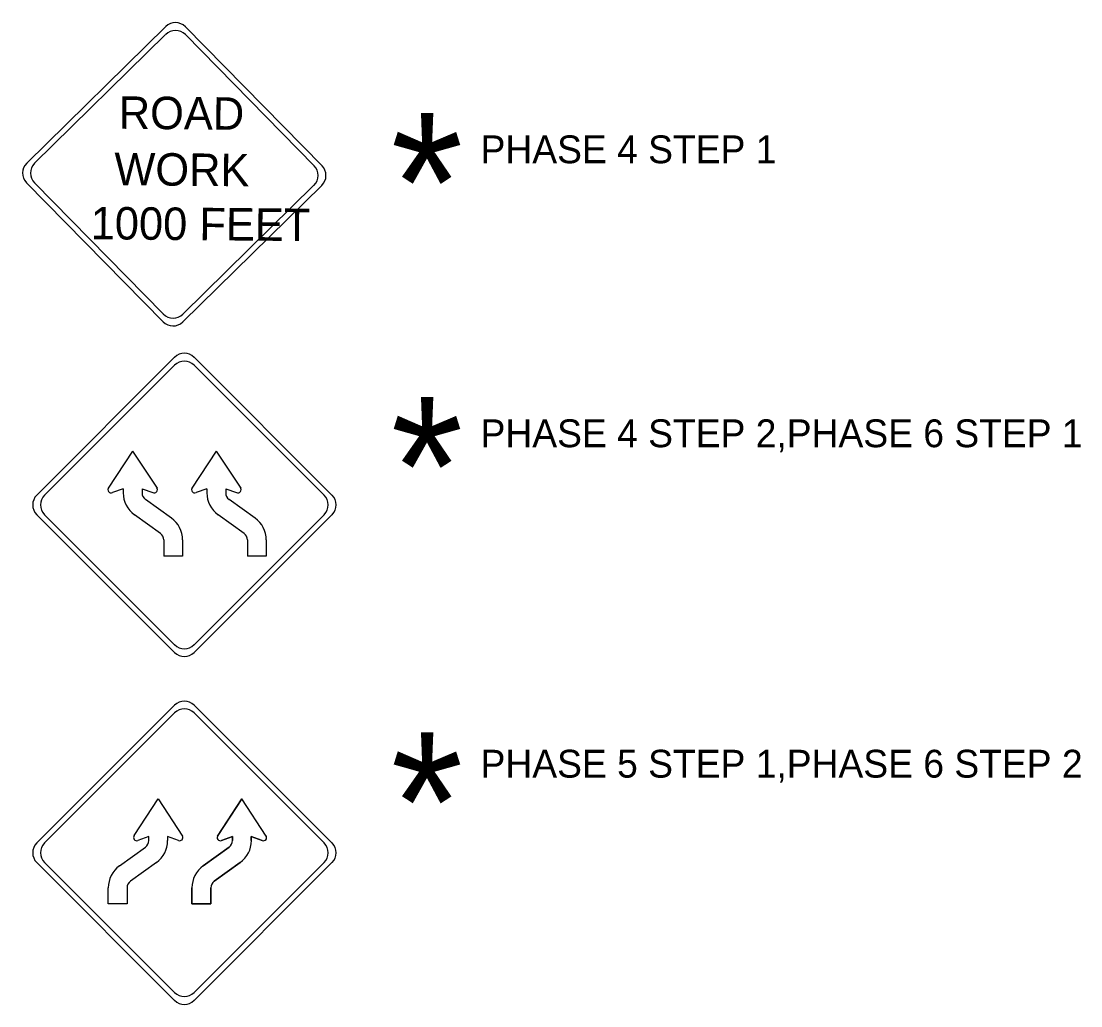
# Model space of a CAD drawing. Extents: x 2155255 to 2162649, y 140388 to 141878.
# Drawn here: x 2158429.7 to 2158658, y 141666 to 141878.2 of the extents above; entities that cross this region are included whole.
import ezdxf

# ---------------------------------------------------------------- set-up
doc = ezdxf.new("R2010")
doc.units = 0
for name, color, linetype in [('Default', 7, 'Continuous'), ('PR_Traffic_Control_Devices_Temp', 7, 'Continuous'), ('PR_Traffic_Control_Devices_Temp_Ph4', 7, 'Continuous')]:
    doc.layers.add(name, color=color, linetype=linetype)

# ---------------------------------------------------------------- blocks, each defined once
blk = doc.blocks.new('W1-4B(L)')
at = {"layer": 'Default'}
for p, q in [((0.0188, 0.2492), (0.2251, 0.4555)), ((0.4608, 0.2492), (0.2545, 0.4555)), ((0.0306, 0.2492), (0.2251, 0.4437)), ((0.449, 0.2492), (0.2545, 0.4437)), ((0.1624, 0.315), (0.1259, 0.2595)), ((0.1624, 0.315), (0.1259, 0.2595)), ((0.1624, 0.315), (0.1259, 0.2595)), ((0.1624, 0.315), (0.1989, 0.2595)), ((0.1624, 0.315), (0.1989, 0.2595)), ((0.1624, 0.315), (0.1989, 0.2595)), ((0.2876, 0.315), (0.2512, 0.2595)), ((0.2876, 0.315), (0.3241, 0.2595)), ((0.1483, 0.2586), (0.1321, 0.2529)), ((0.1483, 0.2586), (0.1321, 0.2529)), ((0.1483, 0.2586), (0.1321, 0.2529)), ((0.1483, 0.2586), (0.1483, 0.2526)), ((0.1483, 0.2586), (0.1483, 0.2526)), ((0.1483, 0.2586), (0.1483, 0.2526)), ((0.1765, 0.2586), (0.1765, 0.2526)), ((0.1765, 0.2586), (0.1927, 0.2529)), ((0.1765, 0.2586), (0.1765, 0.2526)), ((0.1765, 0.2586), (0.1927, 0.2529)), ((0.1765, 0.2586), (0.1765, 0.2526)), ((0.1765, 0.2586), (0.1927, 0.2529)), ((0.2735, 0.2586), (0.2573, 0.2529)), ((0.2735, 0.2586), (0.2735, 0.2526)), ((0.3017, 0.2586), (0.3017, 0.2526)), ((0.3017, 0.2586), (0.318, 0.2529)), ((0.2204, 0.2148), (0.1815, 0.2428)), ((0.2204, 0.2148), (0.1815, 0.2428)), ((0.2204, 0.2148), (0.1815, 0.2428)), ((0.3457, 0.2148), (0.3068, 0.2428)), ((0.2251, 0.0135), (0.0188, 0.2198)), ((0.2251, 0.0253), (0.0306, 0.2198)), ((0.2039, 0.1919), (0.1651, 0.2199)), ((0.2039, 0.1919), (0.1651, 0.2199)), ((0.2039, 0.1919), (0.1651, 0.2199)), ((0.2545, 0.0135), (0.4608, 0.2198)), ((0.2545, 0.0253), (0.449, 0.2198)), ((0.3292, 0.1919), (0.2903, 0.2199)), ((0.209, 0.1821), (0.209, 0.1579)), ((0.209, 0.1821), (0.209, 0.1579)), ((0.209, 0.1821), (0.209, 0.1579)), ((0.2372, 0.1821), (0.2372, 0.1579)), ((0.2372, 0.1821), (0.2372, 0.1579)), ((0.2372, 0.1821), (0.2372, 0.1579)), ((0.3342, 0.1821), (0.3342, 0.1579)), ((0.3624, 0.1821), (0.3624, 0.1579)), ((0.2372, 0.1579), (0.209, 0.1579)), ((0.2372, 0.1579), (0.209, 0.1579)), ((0.2372, 0.1579), (0.209, 0.1579)), ((0.3624, 0.1579), (0.3342, 0.1579))]:
    blk.add_line(p, q, dxfattribs=at)
for centre, radius, start, end in [((0.2398, 0.4407), 0.0208, 45, 135), ((0.2398, 0.429), 0.0208, 45, 135), ((0.1302, 0.2573), 0.00478, 140.8834, 293.1491), ((0.1302, 0.2573), 0.00478, 140.8834, 293.1491), ((0.1302, 0.2573), 0.00478, 140.8834, 293.1491), ((0.1946, 0.2573), 0.00478, 246.8509, 39.1166), ((0.1946, 0.2573), 0.00478, 246.8509, 39.1166), ((0.1946, 0.2573), 0.00478, 246.8509, 39.1166), ((0.2554, 0.2573), 0.00478, 140.8834, 293.1491), ((0.3199, 0.2573), 0.00478, 246.8509, 39.1166), ((0.0336, 0.2345), 0.0208, 135, 225), ((0.0454, 0.2345), 0.0208, 135, 225), ((0.1886, 0.2526), 0.0403, 180, 234.2678), ((0.1886, 0.2526), 0.0403, 180, 234.2678), ((0.1886, 0.2526), 0.0403, 180, 234.2678), ((0.1886, 0.2526), 0.0121, 180, 234.2678), ((0.1886, 0.2526), 0.0121, 180, 234.2678), ((0.1886, 0.2526), 0.0121, 180, 234.2678), ((0.3138, 0.2526), 0.0403, 180, 234.2678), ((0.3138, 0.2526), 0.0121, 180, 234.2678), ((0.4343, 0.2345), 0.0208, 315, 45), ((0.4461, 0.2345), 0.0208, 315, 45), ((0.1969, 0.1821), 0.0403, 0, 54.2678), ((0.1969, 0.1821), 0.0403, 0, 54.2678), ((0.1969, 0.1821), 0.0403, 0, 54.2678), ((0.3221, 0.1821), 0.0403, 0, 54.2678), ((0.1969, 0.1821), 0.0121, 0, 54.2678), ((0.1969, 0.1821), 0.0121, 0, 54.2678), ((0.1969, 0.1821), 0.0121, 0, 54.2678), ((0.3221, 0.1821), 0.0121, 0, 54.2678), ((0.2398, 0.0401), 0.0208, 225, 315), ((0.2398, 0.0283), 0.0208, 225, 315)]:
    blk.add_arc(centre, radius, start, end, dxfattribs=at)
blk = doc.blocks.new('W1-4B(R)e')
at = {"layer": 'Default'}
for p, q in [((0.0188, 0.2492), (0.2251, 0.4555)), ((0.4608, 0.2492), (0.2545, 0.4555)), ((0.0306, 0.2492), (0.2251, 0.4437)), ((0.449, 0.2492), (0.2545, 0.4437)), ((0.2251, 0.0135), (0.0188, 0.2198)), ((0.2251, 0.0253), (0.0306, 0.2198)), ((0.2545, 0.0135), (0.4608, 0.2198)), ((0.2545, 0.0253), (0.449, 0.2198))]:
    blk.add_line(p, q, dxfattribs=at)
for points in [[(0.1648, 0.2603), (0.2007, 0.315), (0.2372, 0.2595)], [(0.2895, 0.2595), (0.3259, 0.315)], [(0.3624, 0.2595), (0.3259, 0.315), (0.29, 0.2603)], [(0.3624, 0.2595), (0.3259, 0.315)], [(0.1866, 0.2526), (0.1866, 0.2586), (0.1704, 0.2529)], [(0.231, 0.2529), (0.2148, 0.2586), (0.2148, 0.2526)], [(0.2956, 0.2529), (0.2956, 0.2529), (0.3119, 0.2586), (0.3119, 0.2526), (0.3119, 0.2526)], [(0.3119, 0.2526), (0.3119, 0.2586), (0.2956, 0.2529)], [(0.2956, 0.2529), (0.3119, 0.2586), (0.3119, 0.2526)], [(0.34, 0.2526), (0.34, 0.2586), (0.3563, 0.2529), (0.3563, 0.2529)], [(0.34, 0.2526), (0.34, 0.2586), (0.3563, 0.2529)], [(0.3563, 0.2529), (0.34, 0.2586), (0.34, 0.2526)], [(0.1427, 0.2148), (0.1816, 0.2428)], [(0.3068, 0.2428), (0.3068, 0.2428), (0.2679, 0.2148), (0.2679, 0.2148)], [(0.2679, 0.2148), (0.3068, 0.2428)], [(0.3068, 0.2428), (0.2679, 0.2148)], [(0.198, 0.2199), (0.1592, 0.1919)], [(0.2844, 0.1919), (0.3233, 0.2199), (0.3233, 0.2199)], [(0.3233, 0.2199), (0.2844, 0.1919)], [(0.2844, 0.1919), (0.3233, 0.2199)], [(0.1541, 0.1821), (0.1541, 0.1579), (0.1259, 0.1579), (0.1259, 0.1821)], [(0.2512, 0.1821), (0.2512, 0.1579), (0.2794, 0.1579), (0.2794, 0.1821), (0.2794, 0.1821)], [(0.2794, 0.1821), (0.2794, 0.1579), (0.2512, 0.1579), (0.2512, 0.1821)], [(0.2512, 0.1821), (0.2512, 0.1579), (0.2794, 0.1579), (0.2794, 0.1821)]]:
    blk.add_lwpolyline(points, dxfattribs=at)
for centre, radius, start, end in [((0.2398, 0.4407), 0.0208, 45, 135), ((0.2398, 0.429), 0.0208, 45, 135), ((0.1685, 0.2573), 0.00478, 140.8834, 293.1491), ((0.2329, 0.2573), 0.00478, 246.8509, 27.4548), ((0.2937, 0.2573), 0.00478, 140.8834, 293.1491), ((0.2937, 0.2573), 0.00478, 140.8834, 293.1491), ((0.2937, 0.2573), 0.00478, 140.8834, 293.1491), ((0.3582, 0.2573), 0.00478, 246.8509, 39.1166), ((0.3582, 0.2573), 0.00478, 246.8509, 39.1166), ((0.3582, 0.2573), 0.00478, 246.8509, 27.4548), ((0.0336, 0.2345), 0.0208, 135, 225), ((0.0454, 0.2345), 0.0208, 135, 225), ((0.1745, 0.2526), 0.0121, 305.7322, 360), ((0.1745, 0.2526), 0.0403, 305.7322, 360), ((0.2998, 0.2526), 0.0121, 305.7322, 0), ((0.2998, 0.2526), 0.0121, 305.7322, 360), ((0.2998, 0.2526), 0.0121, 305.7322, 0), ((0.2998, 0.2526), 0.0403, 305.7322, 0), ((0.2998, 0.2526), 0.0403, 305.7322, 360), ((0.2998, 0.2526), 0.0403, 305.7322, 0), ((0.4343, 0.2345), 0.0208, 315, 45), ((0.4461, 0.2345), 0.0208, 315, 45), ((0.1662, 0.1821), 0.0403, 125.7322, 180), ((0.2915, 0.1821), 0.0403, 125.7322, 180), ((0.2915, 0.1821), 0.0403, 125.7322, 180), ((0.2915, 0.1821), 0.0403, 125.7322, 180), ((0.1662, 0.1821), 0.0121, 125.7322, 180), ((0.2915, 0.1821), 0.0121, 125.7322, 180), ((0.2915, 0.1821), 0.0121, 125.7322, 180), ((0.2915, 0.1821), 0.0121, 125.7322, 180), ((0.2398, 0.0401), 0.0208, 225, 315), ((0.2398, 0.0283), 0.0208, 225, 315)]:
    blk.add_arc(centre, radius, start, end, dxfattribs=at)
blk = doc.blocks.new('Cw20-1_none')
at = {"layer": 'Default'}
for p, q in [((0.177, 3.005), (2.651, 5.48)), ((0.318, 3.005), (2.651, 5.339)), ((5.48, 3.005), (3.005, 5.48)), ((5.338, 3.005), (3.005, 5.339)), ((2.651, 0.177), (0.177, 2.652)), ((2.651, 0.318), (0.318, 2.652)), ((3.005, 0.177), (5.48, 2.652)), ((3.005, 0.318), (5.338, 2.652))]:
    blk.add_line(p, q, dxfattribs=at)
for centre, start, end in [((2.828, 5.303), 45, 135), ((2.828, 5.162), 45, 135), ((0.353, 2.828), 135, 225), ((0.495, 2.828), 135, 225), ((5.162, 2.828), 315, 45), ((5.303, 2.828), 315, 45), ((2.828, 0.495), 225, 315), ((2.828, 0.354), 225, 315)]:
    blk.add_arc(centre, 0.25, start, end, dxfattribs=at)
for s, p in [('ROAD', (1.821, 3.637)), ('WORK', (1.751, 2.623))]:
    blk.add_text(s, height=0.5833, dxfattribs=at).set_placement(p)

msp = doc.modelspace()

# ---------------------------------------------------------------- block references
at = {"layer": 'PR_Traffic_Control_Devices_Temp', "xscale": 144, "yscale": 144}
for name, p in [('W1-4B(L)', (2158430.29, 141740.16)), ('W1-4B(R)e', (2158430.29, 141665.19))]:
    msp.add_blockref(name, p, dxfattribs=at)
at = {"layer": 'PR_Traffic_Control_Devices_Temp_Ph4', "xscale": 12, "yscale": 12, "rotation": -0.5014925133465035}
msp.add_blockref('Cw20-1_none', (2158428.42, 141811.56), dxfattribs=at)

# ---------------------------------------------------------------- texts
at = {"layer": 'PR_Traffic_Control_Devices_Temp'}
for s, height, p in [('*', 30, (2158509.3, 141828.42)), ('PHASE 4 STEP 1', 6, (2158528.67, 141847.58)), ('*', 30, (2158509.3, 141767.21)), ('PHASE 4 STEP 2,PHASE 6 STEP 1', 6, (2158528.67, 141786.37)), ('*', 30, (2158509.3, 141694.88)), ('PHASE 5 STEP 1,PHASE 6 STEP 2', 6, (2158528.67, 141715.15))]:
    msp.add_text(s, height=height, dxfattribs=at).set_placement(p)
at = {"layer": 'PR_Traffic_Control_Devices_Temp_Ph4'}
msp.add_text('1000 FEET', height=7, rotation=359.4985, dxfattribs=at).set_placement((2158444.6, 141831.2))

doc.saveas('drawing.dxf')
